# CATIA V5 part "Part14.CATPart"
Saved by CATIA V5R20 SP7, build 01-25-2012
Part number: squelette tige vérin droit
Bounding box of the stored display mesh (mm): x 0.841 to 11.46, y -5.049 to 23, z -6.405 to -5.721
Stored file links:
  F:\Travaux\Modélisations\CFAO_2011\CFAO_2011_MMS\CFAO_2011_MMS_DONE\CFAO_2011_MMS_jboiteux\Catia\Part14.CATPart
  U:\finthinkmotion\stepper.CATProduct
  F:\Travaux\Modélisations\CFAO_2011\CFAO_2011_MMS\CFAO_2011_MMS_DONE\CFAO_2011_MMS_jboiteux\Catia\part3.CATPart
  F:\Travaux\Modélisations\CFAO_2011\CFAO_2011_MMS\CFAO_2011_MMS_DONE\CFAO_2011_MMS_jboiteux\Catia\Part13.CATPart
  F:\Travaux\Modélisations\CFAO_2011\CFAO_2011_MMS\CFAO_2011_MMS_DONE\CFAO_2011_MMS_jboiteux\Catia\Part1.CATPart
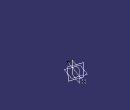
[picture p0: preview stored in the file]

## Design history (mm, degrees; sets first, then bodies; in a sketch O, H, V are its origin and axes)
Set1
  Point1: linked copy from another document
  Point2: linked copy from another document
  Line1: linked copy from another document
  Point3: linked copy from another document
Body1 (main body)
  Point4: type OnCurve, Support Line1, Ratio 0
  Line2: type PtPt, FirstPoint Point4, SecondPoint Point3
  Line3: type PtDir, RefPoint Point4, Direction Line2, Start 0, End 30
  Plane1: type 2Lines, Element1 Line3, Element2 Line1
  Plane2: type Angle, RefPlane Plane1, Direction Line3, Angle 90
  Plane3: type Normal, Curve Line3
